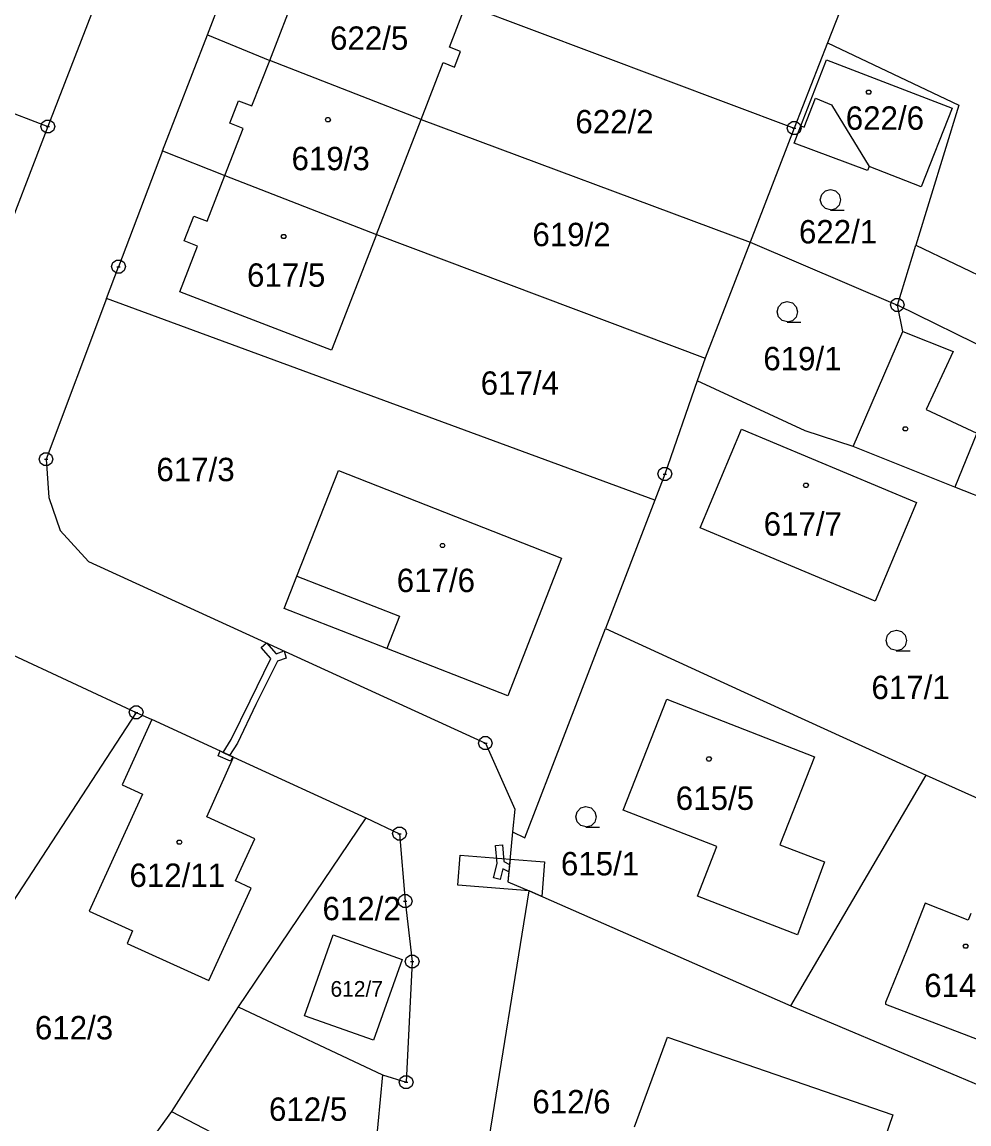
# Model space of a CAD drawing. Extents: x -759060 to -757386, y -1172273 to -1170948.
# Drawn here: x -758181.3 to -758112.4, y -1171511 to -1171430.9 of the extents above; entities that cross this region are included whole.
import ezdxf

# ---------------------------------------------------------------- set-up
doc = ezdxf.new("R2010")
doc.units = 0
for name, color, linetype in [('Vrstva 1', 7, 'Continuous'), ('Vrstva 12', 7, 'Continuous'), ('Vrstva 13', 7, 'Continuous'), ('Vrstva 2', 7, 'Continuous'), ('Vrstva 3', 7, 'Continuous'), ('Vrstva 4', 7, 'Continuous'), ('Vrstva 5', 7, 'Continuous'), ('Vrstva 8', 7, 'Continuous')]:
    doc.layers.add(name, color=color, linetype=linetype)

msp = doc.modelspace()

# ---------------------------------------------------------------- linework, layer by layer
at = {"layer": 'Vrstva 1'}
for p, q in [((-758170.38, -1171415.15), (-758179.37, -1171438.48)), ((-758167.78, -1171431.82), (-758164.56, -1171423.43)), ((-758207.39, -1171427.77), (-758179.37, -1171438.48)), ((-758150.19, -1171432.71), (-758149, -1171429.63)), ((-758149, -1171429.63), (-758125.12, -1171438.6)), ((-758121.82, -1171430.12), (-758122.71, -1171432.4)), ((-758171.05, -1171440.25), (-758167.78, -1171431.82)), ((-758167.78, -1171431.82), (-758163.25, -1171433.67)), ((-758122.71, -1171432.4), (-758125.12, -1171438.6)), ((-758122.71, -1171432.4), (-758113.15, -1171436.92)), ((-758149.39, -1171433.02), (-758150.19, -1171432.71)), ((-758149.82, -1171434.15), (-758149.39, -1171433.02)), ((-758152.23, -1171437.96), (-758163.25, -1171433.67)), ((-758152.23, -1171437.96), (-758150.63, -1171433.83)), ((-758150.63, -1171433.83), (-758149.82, -1171434.15)), ((-758124.65, -1171438.42), (-758122.78, -1171433.63)), ((-758122.78, -1171433.63), (-758113.64, -1171437.14)), ((-758113.15, -1171436.92), (-758116.29, -1171447.1)), ((-758113.64, -1171437.14), (-758115.91, -1171442.85)), ((-758155.48, -1171446.31), (-758152.23, -1171437.96)), ((-758152.23, -1171437.96), (-758128.33, -1171446.89)), ((-758179.37, -1171438.48), (-758187.54, -1171459.66)), ((-758125.12, -1171438.6), (-758128.33, -1171446.89)), ((-758125.14, -1171439.69), (-758124.65, -1171438.42)), ((-758119.79, -1171441.68), (-758125.14, -1171439.69)), ((-758171.05, -1171440.25), (-758174.23, -1171448.66)), ((-758171.05, -1171440.25), (-758166.5, -1171442.04)), ((-758119.68, -1171441.37), (-758119.79, -1171441.68)), ((-758115.91, -1171442.85), (-758119.68, -1171441.37)), ((-758167.79, -1171445.36), (-758166.5, -1171442.04)), ((-758166.5, -1171442.04), (-758155.48, -1171446.31)), ((-758169.46, -1171446.78), (-758168.76, -1171444.98)), ((-758168.76, -1171444.98), (-758167.79, -1171445.36)), ((-758155.48, -1171446.31), (-758158.75, -1171454.74)), ((-758155.48, -1171446.31), (-758131.6, -1171455.31)), ((-758168.49, -1171447.16), (-758169.46, -1171446.78)), ((-758128.33, -1171446.89), (-758131.6, -1171455.31)), ((-758128.33, -1171446.89), (-758117.63, -1171451.45)), ((-758117.63, -1171451.45), (-758116.29, -1171447.1)), ((-758116.29, -1171447.1), (-758099.8, -1171455.02)), ((-758169.77, -1171450.48), (-758168.49, -1171447.16)), ((-758175.1, -1171450.98), (-758174.23, -1171448.66)), ((-758175.1, -1171450.98), (-758179.5, -1171462.66)), ((-758135.26, -1171465.64), (-758175.1, -1171450.98)), ((-758158.75, -1171454.74), (-758169.77, -1171450.48)), ((-758101.51, -1171459.4), (-758117.63, -1171451.45)), ((-758117.24, -1171453.38), (-758117.63, -1171451.45)), ((-758120.83, -1171461.74), (-758117.24, -1171453.38)), ((-758131.6, -1171455.31), (-758132.17, -1171456.95)), ((-758132.17, -1171456.95), (-758134.53, -1171463.73)), ((-758124.32, -1171460.59), (-758132.17, -1171456.95)), ((-758131.96, -1171467.65), (-758128.96, -1171460.48)), ((-758128.96, -1171460.48), (-758116.25, -1171465.81)), ((-758120.83, -1171461.74), (-758124.32, -1171460.59)), ((-758113.46, -1171464.68), (-758120.83, -1171461.74)), ((-758179.5, -1171462.66), (-758179.31, -1171465.44)), ((-758161.27, -1171471.16), (-758158.25, -1171463.47)), ((-758158.25, -1171463.47), (-758142.03, -1171469.84)), ((-758134.53, -1171463.73), (-758135.26, -1171465.64)), ((-758104.65, -1171468.2), (-758113.46, -1171464.68)), ((-758179.31, -1171465.44), (-758178.47, -1171467.83)), ((-758135.26, -1171465.64), (-758138.85, -1171474.96)), ((-758116.25, -1171465.81), (-758119.24, -1171472.98)), ((-758178.47, -1171467.83), (-758176.43, -1171470.08)), ((-758119.24, -1171472.98), (-758131.96, -1171467.65)), ((-758176.43, -1171470.08), (-758147.57, -1171483.29)), ((-758142.03, -1171469.84), (-758145.94, -1171479.85)), ((-758162.19, -1171473.51), (-758161.27, -1171471.16)), ((-758154.74, -1171476.42), (-758162.19, -1171473.51)), ((-758144.7, -1171490.17), (-758138.85, -1171474.96)), ((-758138.85, -1171474.96), (-758128.76, -1171479.59)), ((-758182.3, -1171476.7), (-758172.95, -1171481.06)), ((-758145.94, -1171479.85), (-758154.74, -1171476.42)), ((-758128.76, -1171479.59), (-758115.54, -1171485.61)), ((-758137.55, -1171488.15), (-758134.38, -1171480.1)), ((-758134.38, -1171480.1), (-758123.66, -1171484.29)), ((-758172.95, -1171481.06), (-758186.5, -1171501.82)), ((-758172.95, -1171481.06), (-758171.82, -1171481.58)), ((-758171.82, -1171481.58), (-758173.98, -1171486.31)), ((-758165.88, -1171484.31), (-758171.82, -1171481.58)), ((-758147.57, -1171483.29), (-758145.44, -1171488.1)), ((-758167.83, -1171488.65), (-758165.88, -1171484.31)), ((-758165.88, -1171484.31), (-758156.26, -1171488.72)), ((-758123.66, -1171484.29), (-758126.17, -1171490.68)), ((-758173.98, -1171486.31), (-758172.49, -1171486.99)), ((-758125.36, -1171502.37), (-758115.54, -1171485.61)), ((-758115.54, -1171485.61), (-758110.52, -1171487.88)), ((-758172.49, -1171486.99), (-758176.37, -1171495.5)), ((-758164.34, -1171490.24), (-758167.83, -1171488.65)), ((-758156.26, -1171488.72), (-758165.54, -1171502.46)), ((-758156.26, -1171488.72), (-758153.81, -1171489.87)), ((-758145.44, -1171488.1), (-758145.59, -1171489.74)), ((-758130.74, -1171490.81), (-758137.55, -1171488.15)), ((-758165.73, -1171493.3), (-758164.34, -1171490.24)), ((-758153.81, -1171489.87), (-758153.4, -1171494.78)), ((-758145.59, -1171489.74), (-758145.93, -1171493.36)), ((-758145.59, -1171489.74), (-758144.7, -1171490.17)), ((-758132.16, -1171494.4), (-758130.74, -1171490.81)), ((-758126.17, -1171490.68), (-758122.92, -1171491.92)), ((-758122.92, -1171491.92), (-758124.89, -1171497.22)), ((-758164.6, -1171493.83), (-758165.73, -1171493.3)), ((-758145.93, -1171493.36), (-758144.4, -1171494.03)), ((-758167.68, -1171500.55), (-758164.6, -1171493.83)), ((-758148.65, -1171520.31), (-758144.4, -1171494.03)), ((-758144.4, -1171494.03), (-758125.36, -1171502.37)), ((-758153.4, -1171494.78), (-758152.89, -1171499.17)), ((-758124.89, -1171497.22), (-758132.16, -1171494.4)), ((-758176.37, -1171495.5), (-758173.21, -1171496.94)), ((-758173.21, -1171496.94), (-758173.61, -1171497.86)), ((-758160.72, -1171503.1), (-758158.64, -1171497.22)), ((-758158.64, -1171497.22), (-758153.63, -1171499.02)), ((-758173.61, -1171497.86), (-758167.68, -1171500.55)), ((-758153.63, -1171499.02), (-758155.71, -1171504.87)), ((-758152.89, -1171499.17), (-758153.33, -1171507.94)), ((-758125.36, -1171502.37), (-758111.12, -1171508.38)), ((-758165.54, -1171502.46), (-758170.39, -1171510.05)), ((-758165.54, -1171502.46), (-758155.04, -1171507.39)), ((-758155.71, -1171504.87), (-758160.72, -1171503.1)), ((-758136.74, -1171511.17), (-758134.34, -1171504.66)), ((-758134.34, -1171504.66), (-758117.97, -1171510.31)), ((-758155.04, -1171507.39), (-758156.02, -1171517.34)), ((-758155.04, -1171507.39), (-758153.33, -1171507.94)), ((-758170.39, -1171510.05), (-758172.63, -1171513.14)), ((-758170.39, -1171510.05), (-758160.43, -1171515.23)), ((-758117.97, -1171510.31), (-758122.06, -1171522.35))]:
    msp.add_line(p, q, dxfattribs=at)
at = {"layer": 'Vrstva 12'}
for p, q in [((-758163.25, -1171433.67), (-758161.94, -1171430.28)), ((-758150.19, -1171432.71), (-758149, -1171429.63)), ((-758149.39, -1171433.02), (-758150.19, -1171432.71)), ((-758149.82, -1171434.15), (-758149.39, -1171433.02)), ((-758164.54, -1171436.98), (-758163.25, -1171433.67)), ((-758152.23, -1171437.96), (-758163.25, -1171433.67)), ((-758152.23, -1171437.96), (-758163.25, -1171433.67)), ((-758152.23, -1171437.96), (-758150.63, -1171433.83)), ((-758150.63, -1171433.83), (-758149.82, -1171434.15)), ((-758124.65, -1171438.42), (-758122.78, -1171433.63)), ((-758122.78, -1171433.63), (-758113.64, -1171437.14)), ((-758166.15, -1171438.23), (-758165.52, -1171436.6)), ((-758165.52, -1171436.6), (-758164.54, -1171436.98)), ((-758124.41, -1171438.51), (-758123.59, -1171436.42)), ((-758123.59, -1171436.42), (-758122.41, -1171436.9)), ((-758122.41, -1171436.9), (-758119.68, -1171441.37)), ((-758113.64, -1171437.14), (-758115.91, -1171442.85)), ((-758165.17, -1171438.61), (-758166.15, -1171438.23)), ((-758155.48, -1171446.31), (-758152.23, -1171437.96)), ((-758166.5, -1171442.04), (-758165.17, -1171438.61)), ((-758124.65, -1171438.42), (-758124.41, -1171438.51)), ((-758115.91, -1171442.85), (-758119.68, -1171441.37)), ((-758167.79, -1171445.36), (-758166.5, -1171442.04)), ((-758166.5, -1171442.04), (-758155.48, -1171446.31)), ((-758166.5, -1171442.04), (-758155.48, -1171446.31)), ((-758169.46, -1171446.78), (-758168.76, -1171444.98)), ((-758168.76, -1171444.98), (-758167.79, -1171445.36)), ((-758155.48, -1171446.31), (-758158.75, -1171454.74)), ((-758168.49, -1171447.16), (-758169.46, -1171446.78)), ((-758169.77, -1171450.48), (-758168.49, -1171447.16)), ((-758158.75, -1171454.74), (-758169.77, -1171450.48)), ((-758131.96, -1171467.65), (-758128.96, -1171460.48)), ((-758128.96, -1171460.48), (-758116.25, -1171465.81)), ((-758161.27, -1171471.16), (-758158.25, -1171463.47)), ((-758158.25, -1171463.47), (-758142.03, -1171469.84)), ((-758116.25, -1171465.81), (-758119.24, -1171472.98)), ((-758119.24, -1171472.98), (-758131.96, -1171467.65)), ((-758142.03, -1171469.84), (-758145.94, -1171479.85)), ((-758161.27, -1171471.16), (-758153.82, -1171474.07)), ((-758153.82, -1171474.07), (-758154.74, -1171476.42)), ((-758145.94, -1171479.85), (-758154.74, -1171476.42)), ((-758137.55, -1171488.15), (-758134.38, -1171480.1)), ((-758134.38, -1171480.1), (-758123.66, -1171484.29)), ((-758171.82, -1171481.58), (-758173.98, -1171486.31)), ((-758165.88, -1171484.31), (-758171.82, -1171481.58)), ((-758167.83, -1171488.65), (-758165.88, -1171484.31)), ((-758123.66, -1171484.29), (-758126.17, -1171490.68)), ((-758173.98, -1171486.31), (-758172.49, -1171486.99)), ((-758172.49, -1171486.99), (-758176.37, -1171495.5)), ((-758164.34, -1171490.24), (-758167.83, -1171488.65)), ((-758130.74, -1171490.81), (-758137.55, -1171488.15)), ((-758165.73, -1171493.3), (-758164.34, -1171490.24)), ((-758132.16, -1171494.4), (-758130.74, -1171490.81)), ((-758126.17, -1171490.68), (-758122.92, -1171491.92)), ((-758122.92, -1171491.92), (-758124.89, -1171497.22)), ((-758164.6, -1171493.83), (-758165.73, -1171493.3)), ((-758167.68, -1171500.55), (-758164.6, -1171493.83)), ((-758124.89, -1171497.22), (-758132.16, -1171494.4)), ((-758115.61, -1171494.91), (-758116.92, -1171498.26)), ((-758112.48, -1171496.15), (-758115.61, -1171494.91)), ((-758176.37, -1171495.5), (-758173.21, -1171496.94)), ((-758112.3, -1171495.68), (-758112.48, -1171496.15)), ((-758173.21, -1171496.94), (-758173.61, -1171497.86)), ((-758173.61, -1171497.86), (-758167.68, -1171500.55)), ((-758116.92, -1171498.26), (-758118.48, -1171502.15)), ((-758118.48, -1171502.15), (-758118.5, -1171502.27)), ((-758118.5, -1171502.27), (-758109.88, -1171505.54)), ((-758136.74, -1171511.17), (-758134.34, -1171504.66)), ((-758134.34, -1171504.66), (-758117.97, -1171510.31)), ((-758117.97, -1171510.31), (-758122.06, -1171522.35))]:
    msp.add_line(p, q, dxfattribs=at)
at = {"layer": 'Vrstva 13'}
for p, q in [((-758163.87, -1171476.33), (-758163.49, -1171476)), ((-758163.17, -1171477.13), (-758163.87, -1171476.33)), ((-758163.49, -1171476), (-758162.79, -1171476.8)), ((-758162.79, -1171476.8), (-758162.2, -1171476.59)), ((-758162.2, -1171476.59), (-758162.06, -1171477.11)), ((-758164.68, -1171480.21), (-758163.17, -1171477.13)), ((-758162.69, -1171477.32), (-758164.26, -1171480.49)), ((-758162.06, -1171477.11), (-758162.69, -1171477.32)), ((-758166.04, -1171483.03), (-758164.68, -1171480.21)), ((-758164.26, -1171480.49), (-758165.6, -1171483.29)), ((-758166.63, -1171483.96), (-758166.04, -1171483.03)), ((-758167, -1171484.2), (-758166.85, -1171483.86)), ((-758166.85, -1171483.86), (-758166.63, -1171483.96)), ((-758165.6, -1171483.29), (-758166.16, -1171484.18)), ((-758166.09, -1171484.61), (-758167, -1171484.2)), ((-758166.16, -1171484.18), (-758166.63, -1171483.96)), ((-758166.63, -1171483.96), (-758166.16, -1171484.18)), ((-758166.16, -1171484.18), (-758165.94, -1171484.28)), ((-758165.94, -1171484.28), (-758166.09, -1171484.61)), ((-758146.84, -1171490.73), (-758146.34, -1171490.68)), ((-758146.71, -1171492.04), (-758146.84, -1171490.73)), ((-758146.34, -1171490.68), (-758146.22, -1171491.9)), ((-758149.58, -1171493.62), (-758149.4, -1171491.42)), ((-758149.4, -1171491.42), (-758145.78, -1171491.71)), ((-758146.22, -1171491.9), (-758145.81, -1171492.11)), ((-758145.78, -1171491.71), (-758145.93, -1171493.36)), ((-758145.78, -1171491.71), (-758145.93, -1171493.36)), ((-758145.78, -1171491.71), (-758143.28, -1171491.91)), ((-758143.28, -1171491.91), (-758143.48, -1171494.43)), ((-758146.99, -1171493.08), (-758146.71, -1171492.04)), ((-758146.3, -1171492.42), (-758146.51, -1171493.2)), ((-758145.86, -1171492.64), (-758146.3, -1171492.42)), ((-758145.81, -1171492.11), (-758145.86, -1171492.64)), ((-758146.51, -1171493.2), (-758146.99, -1171493.08)), ((-758145.93, -1171493.36), (-758144.4, -1171494.03)), ((-758145.93, -1171493.36), (-758144.4, -1171494.03)), ((-758144.4, -1171494.03), (-758149.58, -1171493.62)), ((-758143.48, -1171494.43), (-758144.4, -1171494.03))]:
    msp.add_line(p, q, dxfattribs=at)
at = {"layer": 'Vrstva 3'}
for points in [[(-758122.48, -1171444.53), (-758122.86, -1171444.43), (-758123.13, -1171444.16), (-758123.23, -1171443.79), (-758123.13, -1171443.42), (-758122.86, -1171443.15), (-758122.49, -1171443.05), (-758122.12, -1171443.15), (-758121.85, -1171443.42), (-758121.75, -1171443.8), (-758121.85, -1171444.18), (-758122.12, -1171444.45), (-758122.5, -1171444.55), (-758121.5, -1171444.55)], [(-758125.62, -1171452.68), (-758126, -1171452.58), (-758126.27, -1171452.31), (-758126.37, -1171451.94), (-758126.27, -1171451.57), (-758126, -1171451.3), (-758125.63, -1171451.2), (-758125.26, -1171451.3), (-758124.99, -1171451.57), (-758124.89, -1171451.95), (-758124.99, -1171452.33), (-758125.26, -1171452.6), (-758125.64, -1171452.7), (-758124.64, -1171452.7)], [(-758117.69, -1171476.56), (-758118.07, -1171476.46), (-758118.34, -1171476.19), (-758118.44, -1171475.82), (-758118.34, -1171475.45), (-758118.07, -1171475.18), (-758117.7, -1171475.08), (-758117.33, -1171475.18), (-758117.06, -1171475.45), (-758116.96, -1171475.83), (-758117.06, -1171476.21), (-758117.33, -1171476.48), (-758117.71, -1171476.58), (-758116.71, -1171476.58)], [(-758140.25, -1171489.38), (-758140.63, -1171489.28), (-758140.9, -1171489.01), (-758141, -1171488.64), (-758140.9, -1171488.27), (-758140.63, -1171488), (-758140.26, -1171487.9), (-758139.89, -1171488), (-758139.62, -1171488.27), (-758139.52, -1171488.65), (-758139.62, -1171489.03), (-758139.89, -1171489.3), (-758140.27, -1171489.4), (-758139.27, -1171489.4)]]:
    msp.add_lwpolyline(points, dxfattribs=at)
at = {"layer": 'Vrstva 4'}
for p, q in [((-758163.25, -1171433.67), (-758161.94, -1171430.28)), ((-758164.54, -1171436.98), (-758163.25, -1171433.67)), ((-758166.15, -1171438.23), (-758165.52, -1171436.6)), ((-758165.52, -1171436.6), (-758164.54, -1171436.98)), ((-758124.41, -1171438.51), (-758123.59, -1171436.42)), ((-758123.59, -1171436.42), (-758122.41, -1171436.9)), ((-758122.41, -1171436.9), (-758119.68, -1171441.37)), ((-758165.17, -1171438.61), (-758166.15, -1171438.23)), ((-758166.5, -1171442.04), (-758165.17, -1171438.61)), ((-758124.65, -1171438.42), (-758124.41, -1171438.51)), ((-758117.24, -1171453.38), (-758113.58, -1171454.82)), ((-758113.58, -1171454.82), (-758115.53, -1171459.03)), ((-758115.53, -1171459.03), (-758111.86, -1171460.75)), ((-758111.86, -1171460.75), (-758113.46, -1171464.68)), ((-758161.27, -1171471.16), (-758153.82, -1171474.07)), ((-758153.82, -1171474.07), (-758154.74, -1171476.42)), ((-758115.61, -1171494.91), (-758116.92, -1171498.26)), ((-758112.48, -1171496.15), (-758115.61, -1171494.91)), ((-758112.3, -1171495.68), (-758112.48, -1171496.15)), ((-758116.92, -1171498.26), (-758118.48, -1171502.15)), ((-758118.48, -1171502.15), (-758118.5, -1171502.27)), ((-758118.5, -1171502.27), (-758109.88, -1171505.54))]:
    msp.add_line(p, q, dxfattribs=at)
at = {"layer": 'Vrstva 5'}
for points in [[(-758119.62, -1171435.82), (-758119.53, -1171435.97), (-758119.62, -1171436.12), (-758119.8, -1171436.12), (-758119.89, -1171435.97), (-758119.8, -1171435.82)], [(-758158.93, -1171437.83), (-758158.84, -1171437.98), (-758158.93, -1171438.13), (-758159.11, -1171438.13), (-758159.2, -1171437.98), (-758159.11, -1171437.83)], [(-758162.15, -1171446.32), (-758162.06, -1171446.47), (-758162.15, -1171446.62), (-758162.33, -1171446.62), (-758162.42, -1171446.47), (-758162.33, -1171446.32)], [(-758116.95, -1171460.3), (-758116.86, -1171460.45), (-758116.95, -1171460.6), (-758117.13, -1171460.6), (-758117.22, -1171460.45), (-758117.13, -1171460.3)], [(-758124.19, -1171464.4), (-758124.1, -1171464.55), (-758124.19, -1171464.7), (-758124.37, -1171464.7), (-758124.46, -1171464.55), (-758124.37, -1171464.4)], [(-758150.6, -1171468.77), (-758150.51, -1171468.92), (-758150.6, -1171469.07), (-758150.78, -1171469.07), (-758150.87, -1171468.92), (-758150.78, -1171468.77)], [(-758131.24, -1171484.29), (-758131.15, -1171484.44), (-758131.24, -1171484.59), (-758131.42, -1171484.59), (-758131.51, -1171484.44), (-758131.42, -1171484.29)], [(-758169.72, -1171490.34), (-758169.63, -1171490.49), (-758169.72, -1171490.64), (-758169.9, -1171490.64), (-758169.99, -1171490.49), (-758169.9, -1171490.34)], [(-758112.57, -1171497.89), (-758112.48, -1171498.04), (-758112.57, -1171498.19), (-758112.75, -1171498.19), (-758112.84, -1171498.04), (-758112.75, -1171497.89)]]:
    msp.add_lwpolyline(points, close=True, dxfattribs=at)
at = {"layer": 'Vrstva 8'}
for p, q in [((-758179.49, -1171438.48), (-758179.25, -1171438.48)), ((-758125.24, -1171438.6), (-758125, -1171438.6)), ((-758174.35, -1171448.66), (-758174.11, -1171448.66)), ((-758117.75, -1171451.45), (-758117.51, -1171451.45)), ((-758179.62, -1171462.66), (-758179.38, -1171462.66)), ((-758134.65, -1171463.73), (-758134.41, -1171463.73)), ((-758173.07, -1171481.06), (-758172.83, -1171481.06)), ((-758147.69, -1171483.29), (-758147.45, -1171483.29)), ((-758153.93, -1171489.87), (-758153.69, -1171489.87)), ((-758153.52, -1171494.78), (-758153.28, -1171494.78)), ((-758153.01, -1171499.17), (-758152.77, -1171499.17)), ((-758153.45, -1171507.94), (-758153.21, -1171507.94))]:
    msp.add_line(p, q, dxfattribs=at)
for points in [[(-758179.22, -1171438), (-758178.97, -1171438.18), (-758178.87, -1171438.47), (-758178.97, -1171438.76), (-758179.22, -1171438.94), (-758179.53, -1171438.94), (-758179.78, -1171438.76), (-758179.88, -1171438.47), (-758179.78, -1171438.18), (-758179.53, -1171438)], [(-758124.97, -1171438.12), (-758124.72, -1171438.3), (-758124.62, -1171438.59), (-758124.72, -1171438.88), (-758124.97, -1171439.06), (-758125.28, -1171439.06), (-758125.53, -1171438.88), (-758125.63, -1171438.59), (-758125.53, -1171438.3), (-758125.28, -1171438.12)], [(-758174.08, -1171448.18), (-758173.83, -1171448.36), (-758173.73, -1171448.65), (-758173.83, -1171448.94), (-758174.08, -1171449.12), (-758174.39, -1171449.12), (-758174.64, -1171448.94), (-758174.74, -1171448.65), (-758174.64, -1171448.36), (-758174.39, -1171448.18)], [(-758117.48, -1171450.97), (-758117.23, -1171451.15), (-758117.13, -1171451.44), (-758117.23, -1171451.73), (-758117.48, -1171451.91), (-758117.79, -1171451.91), (-758118.04, -1171451.73), (-758118.14, -1171451.44), (-758118.04, -1171451.15), (-758117.79, -1171450.97)], [(-758179.35, -1171462.18), (-758179.1, -1171462.36), (-758179, -1171462.65), (-758179.1, -1171462.94), (-758179.35, -1171463.12), (-758179.66, -1171463.12), (-758179.91, -1171462.94), (-758180.01, -1171462.65), (-758179.91, -1171462.36), (-758179.66, -1171462.18)], [(-758134.38, -1171463.25), (-758134.13, -1171463.43), (-758134.03, -1171463.72), (-758134.13, -1171464.01), (-758134.38, -1171464.19), (-758134.69, -1171464.19), (-758134.94, -1171464.01), (-758135.04, -1171463.72), (-758134.94, -1171463.43), (-758134.69, -1171463.25)], [(-758172.8, -1171480.58), (-758172.55, -1171480.76), (-758172.45, -1171481.05), (-758172.55, -1171481.34), (-758172.8, -1171481.52), (-758173.11, -1171481.52), (-758173.36, -1171481.34), (-758173.46, -1171481.05), (-758173.36, -1171480.76), (-758173.11, -1171480.58)], [(-758147.42, -1171482.81), (-758147.17, -1171482.99), (-758147.07, -1171483.28), (-758147.17, -1171483.57), (-758147.42, -1171483.75), (-758147.73, -1171483.75), (-758147.98, -1171483.57), (-758148.08, -1171483.28), (-758147.98, -1171482.99), (-758147.73, -1171482.81)], [(-758153.66, -1171489.39), (-758153.41, -1171489.57), (-758153.31, -1171489.86), (-758153.41, -1171490.15), (-758153.66, -1171490.33), (-758153.97, -1171490.33), (-758154.22, -1171490.15), (-758154.32, -1171489.86), (-758154.22, -1171489.57), (-758153.97, -1171489.39)], [(-758153.25, -1171494.3), (-758153, -1171494.48), (-758152.9, -1171494.77), (-758153, -1171495.06), (-758153.25, -1171495.24), (-758153.56, -1171495.24), (-758153.81, -1171495.06), (-758153.91, -1171494.77), (-758153.81, -1171494.48), (-758153.56, -1171494.3)], [(-758152.74, -1171498.69), (-758152.49, -1171498.87), (-758152.39, -1171499.16), (-758152.49, -1171499.45), (-758152.74, -1171499.63), (-758153.05, -1171499.63), (-758153.3, -1171499.45), (-758153.4, -1171499.16), (-758153.3, -1171498.87), (-758153.05, -1171498.69)], [(-758153.18, -1171507.46), (-758152.93, -1171507.64), (-758152.83, -1171507.93), (-758152.93, -1171508.22), (-758153.18, -1171508.4), (-758153.49, -1171508.4), (-758153.74, -1171508.22), (-758153.84, -1171507.93), (-758153.74, -1171507.64), (-758153.49, -1171507.46)]]:
    msp.add_lwpolyline(points, close=True, dxfattribs=at)

# ---------------------------------------------------------------- texts
at = {"layer": 'Vrstva 2'}
for s, height, p in [('622/5', 1.7, (-758158.863, -1171432.9)), ('622/2', 1.7, (-758141.033, -1171438.97)), ('622/6', 1.7, (-758121.38, -1171438.71)), ('619/3', 1.7, (-758161.663, -1171441.65)), ('619/2', 1.7, (-758144.153, -1171447.17)), ('622/1', 1.7, (-758124.782, -1171446.97)), ('617/5', 1.7, (-758164.893, -1171450.12)), ('619/1', 1.7, (-758127.373, -1171456.19)), ('617/4', 1.7, (-758147.913, -1171457.97)), ('617/3', 1.7, (-758171.483, -1171464.25)), ('617/7', 1.7, (-758127.345, -1171468.21)), ('617/6', 1.7, (-758154.015, -1171472.31)), ('617/1', 1.7, (-758119.513, -1171480.09)), ('615/5', 1.7, (-758133.733, -1171488.14)), ('615/1', 1.7, (-758142.083, -1171492.9)), ('612/11', 1.7, (-758173.442, -1171493.74)), ('612/2', 1.7, (-758159.413, -1171496.16)), ('614/1', 1.7, (-758115.677, -1171501.75)), ('612/7', 1.14, (-758158.831, -1171501.72)), ('612/3', 1.7, (-758180.316, -1171504.82)), ('612/6', 1.7, (-758144.163, -1171510.2)), ('612/5', 1.7, (-758163.303, -1171510.74))]:
    msp.add_text(s, height=height, dxfattribs=at).set_placement(p)

doc.saveas('drawing.dxf')
